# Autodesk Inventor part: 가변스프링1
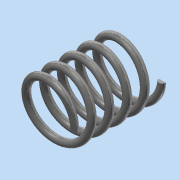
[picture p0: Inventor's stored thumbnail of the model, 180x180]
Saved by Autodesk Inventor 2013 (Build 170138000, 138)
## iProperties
Created: 2018-10
Part Number: 가변스프링1
Material: 스테인리스강
Document SubType Name: Modeling
Designer: Administrator
Density: 8.08 g/cm^3
Mass: 6.26477 g
Surface Area: 15.7515 cm^2
Volume: 0.775342 cm^3
Author: Administrator
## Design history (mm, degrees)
sketch "스케치1"
  geometry: L1 (0, 0)-(8, 0); L2 (0, 0)-(0, 25.151); L3 (0, 25.151)-(8, 25.151); C1 r 1 at (8, 0)
  constraints: 6 end point, 2 perpendicular, 1 centre point, 1 coincident, 1 horizontal
  dimensions: "d0" = 8 distance of L1.start L1.end; "d1" = 25.15059 distance of L1.start L2.end (derived); "d2" = 8 distance of L2.end L3.end; "d3" = 2 diameter of C1
feature "코일1" sketch "스케치1" pitch "d4" = 10; turns "d6" = 5; dims "d5" = 25.15059 (= d1), "d7" = 0, angle "d8" = 90 deg, angle "d9" = 90 deg, "d10" = 0, "d11" = 0
sketch "스케치2"
  geometry: L1 (25.151, 10)-(0, 10); L2 (0, 10)-(0, -10); L3 (0, -10)-(25.151, -10); L4 (25.151, -10)-(25.151, 10); 2 further points
  constraints: 8 end point, 2 parallel, 1 coincident, 1 horizontal, 1 midpoint, 1 perpendicular
  dimensions: "d12" = 25.15059 distance of L1.start L1.end (derived); "d14" = 20 distance of L3.end L1.start
extrude "돌출1" sketch "스케치2" stored distance "d15" = 0; taper "d16" = 0 deg
node "솔리드1"
